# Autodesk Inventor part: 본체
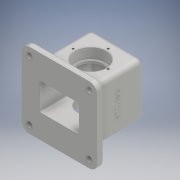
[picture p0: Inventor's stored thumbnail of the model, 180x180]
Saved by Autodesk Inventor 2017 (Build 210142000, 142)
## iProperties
Part Number: 본체
Material: 알루미늄 6061
Document SubType Name: Modeling
Designer: MRC
Density: 2.7 g/cm^3
Appearance: 알루미늄 - 평지
Mass: 1059.83 g
Surface Area: 721.846 cm^2
Volume: 392.53 cm^3
Author: MRC
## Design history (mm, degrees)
sketch "스케치1"
  geometry: L1 (-58, 58)-(58, 58); L2 (58, 58)-(58, -58); L3 (58, -58)-(-58, -58); L4 (-58, -58)-(-58, 58); L5 (-58, 58)-(58, -58); L6 (58, 58)-(-58, -58); 1 further point
  constraints: 12 end point, 2 midpoint, 2 parallel, 2 perpendicular, 1 horizontal
  dimensions: "d0" = 116 distance of L1.end L2.end
extrude "돌출1" new body sketch "스케치1" distance "d1" = 10; taper "d2" = 0 deg
sketch "스케치2" dims "d13" = 12, "d14" = 12, "d15" = 12, "d16" = 12, "d17" = 9
  geometry: L1 (41, -41)-(-41, -41); L2 (-41, -41)-(-41, 41); L3 (-41, 41)-(41, 41); L4 (41, 41)-(41, -41); L5 (41, -41)-(-41, 41); L6 (-41, -41)-(41, 41); 1 further point
  constraints: 12 end point, 2 midpoint, 2 parallel, 2 perpendicular, 1 horizontal
  dimensions: "d3" = 82 distance of L1.end L2.end
extrude "돌출2" join sketch "스케치2" distance "d4" = 80; taper "d5" = 0 deg
sketch "스케치3"
  geometry: L1 (-30, 21)-(30, 21); L2 (30, 21)-(30, -21); L3 (30, -21)-(-30, -21); L4 (-30, -21)-(-30, 21); L5 (-30, 21)-(30, -21); L6 (30, 21)-(-30, -21); 1 further point
  constraints: 12 end point, 2 midpoint, 2 parallel, 1 horizontal, 1 perpendicular
  dimensions: "d6" = 42 distance of L1.end L2.end; "d7" = 60 distance of L2.end L3.end
extrude "돌출3" cut sketch "스케치3" distance "d8" = 80; taper "d9" = 0 deg
sketch "스케치4"
  geometry: C1 r 7.5 at (0, 0); 1 further point
  constraints: 1 centre point, 1 coincident
  dimensions: "d10" = 15 diameter of C1
extrude "돌출4" join sketch "스케치4" distance "d11" = 4; taper "d12" = 0 deg
sketch "스케치5"
  geometry: L1 (58, 58)-(58, -58) reference; L2 (58, -58)-(-58, -58) reference; L3 (-58, -58)-(-58, 58) reference; L4 (-58, 58)-(58, 58) reference; C1 r 4.5 at (46, -46); C2 r 4.5 at (-46, -46); C3 r 4.5 at (-46, 46); C4 r 4.5 at (46, 46); 1 further point
  constraints: 4 centre point, 3 equal radius, 2 horizontal alignment, 2 vertical alignment
  dimensions: "d13" = 12 distance from line of L1 C1.centre; "d14" = 12 distance from line of L2 C1.centre; "d15" = 12 distance from line of L3 C2.centre; "d16" = 12 distance from line of L4 C3.centre; "d17" = 9 diameter of C1
extrude "돌출5" cut sketch "스케치5" distance "d18" = 10; taper "d19" = 0 deg
sketch "스케치6"
  geometry: L1 (99, -10)-(-17, -10) reference; C1 r 23.5 at (41, 38); 2 further points
  constraints: 1 centre point, 1 midpoint, 1 vertical alignment
  dimensions: "d20" = 48 distance from line of L1 C1.centre; "d21" = 47 diameter of C1
extrude "돌출6" cut sketch "스케치6" distance "d22" = 17; taper "d23" = 0 deg
sketch "스케치7"
  geometry: C1 r 20 at (0, 0); C2 r 23.5 at (0, 0) reference; 1 further point
  constraints: 1 centre point, 1 concentric
  dimensions: "d24" = 40 diameter of C1
extrude "돌출7" cut sketch "스케치7" distance "d25" = 3; taper "d26" = 0 deg
sketch "스케치8"
  geometry: C1 r 20 at (41, 38) reference; 5 further points
  constraints: 1 vertical alignment, 5 other
  dimensions: "d27" = 27 distance of C1.centre point (41, 65); "d30" = 360 deg dimension on C1.centre point (41, 65) (derived)
hole "구멍1" sketch "스케치8" at (41, 65), (14, 38), (41, 11), (68, 38) diameter "d32" = 3.242; stored, may be unused: countersink angle "d36" = 90 deg, drill point angle "d38" = 118 deg; dims "d33" = 8, "d34" = 4, "d35" = 2, "d37" = 10
fillet "모깎기1" dims "d39" = 0.6
chamfer "모따기1" distance "d40" = 1; stored, may be unused: second distance "d41" = 2, angle "d42" = 45 deg
hole "구멍2" diameter "d45" = 4.917; stored, may be unused: countersink angle "d49" = 90 deg, drill point angle "d51" = 0 deg; dims "d46" = 17, "d47" = 4, "d48" = 2, "d50" = 17, "d52" = 10, "d53" = 10
chamfer "모따기2" distance "d54" = 1; stored, may be unused: second distance "d55" = 2, angle "d56" = 45 deg
fillet "모깎기2" dims "d57" = 8
fillet "모깎기3" dims "d58" = 8
fillet "모깎기4" dims "d59" = 12
fillet "모깎기5" dims "d60" = 3
sketch "스케치9"
  geometry: L1 (79, -82)-(-13, -82) reference; 3 further points
  constraints: 1 midpoint, 1 vertical alignment, 1 other
  dimensions: "d61" = 48 distance from line of L1 point (33, -34)
extrude "돌출8" join sketch "스케치9" distance "d62" = 0.5; taper "d63" = 0 deg
node "솔리드1"
mirror "미러1"
